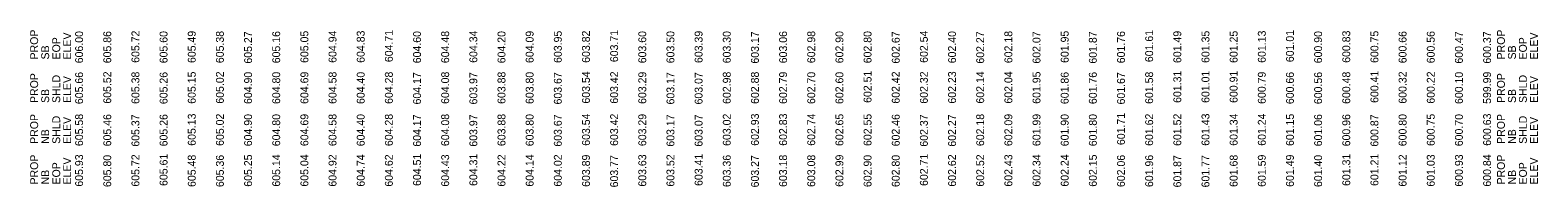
# Model space of a CAD drawing. Extents: x 24273 to 25612, y -285 to 1010.
# Drawn here: x 24273 to 25612, y -285 to -146 of the extents above; entities that cross this region are included whole.
import ezdxf

# ---------------------------------------------------------------- set-up
doc = ezdxf.new("R2010")
doc.units = 0
for name, color, linetype in [('PF_P_Text', 7, 'Continuous'), ('PF_P_Text_Strip_Grades_20', 7, 'Continuous'), ('PF_P_Text_Strip_Grades_LT', 7, 'Continuous'), ('PF_P_Text_Strip_Grades_RT', 7, 'Continuous')]:
    doc.layers.add(name, color=color, linetype=linetype)

msp = doc.modelspace()

# ---------------------------------------------------------------- texts
at = {"layer": 'PF_P_Text'}
for s, p in [('PROP ', (24280.4, -171.7)), ('PROP ', (25582.6, -171.7)), ('SB ', (24290.2, -171.7)), ('EOP', (24300, -171.7)), ('ELEV', (24309.7, -171.7)), ('SB ', (25592.4, -171.7)), ('EOP', (25602.1, -171.7)), ('ELEV', (25611.9, -171.7)), ('PROP ', (24280.4, -210.4)), ('SHLD ', (24300, -210.4)), ('ELEV', (24309.7, -210.4)), ('PROP ', (25582.6, -210.4)), ('SHLD', (25602.1, -210.4)), ('ELEV', (25611.9, -210.4)), ('SB ', (24290.2, -210.4)), ('SB ', (25592.4, -210.4)), ('PROP ', (24280.4, -246.7)), ('SHLD', (24300, -246.7)), ('ELEV', (24309.7, -246.7)), ('PROP ', (25582.6, -246.7)), ('SHLD', (25602.1, -246.7)), ('ELEV', (25611.9, -246.7)), ('NB ', (24290.2, -246.7)), ('NB ', (25592.4, -246.7)), ('PROP ', (24280.4, -282.8)), ('EOP', (24300, -282.8)), ('ELEV', (24309.7, -282.8)), ('PROP ', (25582.6, -282.8)), ('EOP', (25602.1, -282.8)), ('ELEV', (25611.9, -282.8)), ('NB ', (24290.2, -282.8)), ('NB ', (25592.4, -282.8))]:
    msp.add_text(s, height=7, rotation=90, dxfattribs=at).set_placement(p)
at = {"layer": 'PF_P_Text_Strip_Grades_20'}
for s, p in [('605.66', (24320.3, -211.4)), ('605.52', (24345.3, -211)), ('605.38', (24370.3, -211.2)), ('605.26', (24395.3, -211.4)), ('605.15', (24420.3, -211.1)), ('605.02', (24445.3, -211)), ('604.90', (24470.3, -211.3)), ('604.80', (24495.3, -211.3)), ('604.69', (24520.3, -211.2)), ('604.58', (24545.3, -211.2)), ('604.40', (24570.3, -211.3)), ('604.28', (24595.3, -211.2)), ('604.17', (24620.3, -211.7)), ('604.08', (24645.3, -211.2)), ('603.97', (24670.3, -211.7)), ('603.88', (24695.3, -211.2)), ('603.80', (24720.3, -211.3)), ('603.67', (24745.3, -211.7)), ('603.54', (24770.3, -210.9)), ('603.42', (24795.3, -211)), ('603.29', (24820.3, -211.2)), ('603.17', (24845.3, -211.7)), ('603.07', (24870.3, -211.7)), ('602.98', (24895.3, -211.2)), ('602.88', (24920.3, -211.2)), ('602.79', (24945.3, -211.2)), ('602.70', (24970.3, -211.3)), ('602.60', (24995.3, -211.3)), ('602.51', (25020.3, -210.3)), ('602.42', (25045.3, -211)), ('602.32', (25070.3, -211)), ('602.23', (25095.3, -210.9)), ('602.14', (25120.3, -210.9)), ('602.04', (25145.3, -210.9)), ('601.95', (25170.3, -211.1)), ('601.86', (25195.3, -211.4)), ('601.76', (25220.3, -211.4)), ('601.67', (25245.3, -211.7)), ('601.58', (25270.3, -211.2)), ('601.31', (25295.3, -210.3)), ('601.01', (25320.3, -210.3)), ('600.91', (25345.3, -210.3)), ('600.79', (25370.3, -211.2)), ('600.66', (25395.3, -211.4)), ('600.56', (25420.3, -211.4)), ('600.48', (25445.3, -211.2)), ('600.41', (25470.3, -210.3)), ('600.32', (25495.3, -211)), ('600.22', (25520.3, -211)), ('600.10', (25545.3, -211.3)), ('599.99', (25570.3, -211.2)), ('605.58', (24320.3, -248.7)), ('605.46', (24345.3, -248.9)), ('605.37', (24370.3, -249.2)), ('605.26', (24395.3, -248.9)), ('605.13', (24420.3, -248.4)), ('605.02', (24445.3, -248.5)), ('604.90', (24470.3, -248.8)), ('604.80', (24495.3, -248.8)), ('604.69', (24520.3, -248.7)), ('604.58', (24545.3, -248.7)), ('604.40', (24570.3, -248.8)), ('604.28', (24595.3, -248.7)), ('604.17', (24620.3, -249.2)), ('604.08', (24645.3, -248.7)), ('603.97', (24670.3, -249.2)), ('603.88', (24695.3, -248.7)), ('603.80', (24720.3, -248.8)), ('603.67', (24745.3, -249.2)), ('603.54', (24770.3, -248.4)), ('603.42', (24795.3, -248.5)), ('603.29', (24820.3, -248.7)), ('603.17', (24845.3, -249.2)), ('603.07', (24870.3, -249.2)), ('603.02', (24895.3, -248.5)), ('602.93', (24920.3, -248.4)), ('602.83', (24945.3, -248.4)), ('602.74', (24970.3, -248.4)), ('602.65', (24995.3, -248.6)), ('602.55', (25020.3, -248.6)), ('602.46', (25045.3, -248.9)), ('602.37', (25070.3, -249.2)), ('602.27', (25095.3, -249.2)), ('602.18', (25120.3, -248.7)), ('602.09', (25145.3, -248.7)), ('601.99', (25170.3, -248.7)), ('601.90', (25195.3, -248.8)), ('601.80', (25220.3, -248.8)), ('601.71', (25245.3, -247.8)), ('601.62', (25270.3, -248.5)), ('601.52', (25295.3, -248.5)), ('601.43', (25320.3, -248.4)), ('601.34', (25345.3, -248.4)), ('601.24', (25370.3, -248.4)), ('601.15', (25395.3, -248.6)), ('601.06', (25420.3, -248.9)), ('600.96', (25445.3, -248.9)), ('600.87', (25470.3, -249.2)), ('600.80', (25495.3, -248.8)), ('600.75', (25520.3, -248.6)), ('600.70', (25545.3, -248.8)), ('600.63', (25570.3, -248.4))]:
    msp.add_text(s, height=7, rotation=90, dxfattribs=at).set_placement(p)
at = {"layer": 'PF_P_Text_Strip_Grades_LT'}
for s, p in [('606.00', (24320.3, -175.1)), ('605.86', (24345.3, -175.1)), ('605.72', (24370.3, -174.7)), ('605.60', (24395.3, -175.1)), ('605.49', (24420.3, -174.9)), ('605.38', (24445.3, -175)), ('605.16', (24495.3, -175.1)), ('605.05', (24520.3, -174.8)), ('604.94', (24545.3, -174.7)), ('604.83', (24570.3, -174.7)), ('604.71', (24595.3, -174.1)), ('604.60', (24620.3, -175.1)), ('604.48', (24645.3, -175)), ('604.34', (24670.3, -174.7)), ('604.20', (24695.3, -175.1)), ('604.09', (24720.3, -174.9)), ('603.95', (24745.3, -174.8)), ('603.82', (24770.3, -174.7)), ('603.71', (24795.3, -174.1)), ('603.60', (24820.3, -175.1)), ('603.50', (24845.3, -175.1)), ('603.39', (24870.3, -174.9)), ('603.30', (24895.3, -175.1)), ('603.06', (24945.3, -175.1)), ('602.98', (24970.3, -175)), ('602.90', (24995.3, -175.1)), ('602.80', (25020.3, -175.1)), ('602.54', (25070.3, -174.7)), ('602.40', (25095.3, -175.1)), ('602.18', (25145.3, -175)), ('601.95', (25195.3, -174.8)), ('601.76', (25245.3, -175.1)), ('601.61', (25270.3, -174.1)), ('601.49', (25295.3, -174.9)), ('601.35', (25320.3, -174.8)), ('601.25', (25345.3, -174.8)), ('601.13', (25370.3, -174.7)), ('601.01', (25395.3, -174.1)), ('600.90', (25420.3, -175.1)), ('600.83', (25445.3, -174.7)), ('600.75', (25470.3, -174.8)), ('600.66', (25495.3, -175.1)), ('600.56', (25520.3, -175.1)), ('605.27', (24470.3, -175.4)), ('603.17', (24920.3, -175.4)), ('602.67', (25045.3, -175.4)), ('602.27', (25120.3, -175.4)), ('602.07', (25170.3, -175.4)), ('601.87', (25220.3, -175.4)), ('600.47', (25545.3, -175.4)), ('600.37', (25570.3, -175.4))]:
    msp.add_text(s, height=7, rotation=90, dxfattribs=at).set_placement(p)
at = {"layer": 'PF_P_Text_Strip_Grades_RT'}
for s, p in [('605.93', (24320.3, -284.7)), ('605.80', (24345.3, -285.1)), ('605.72', (24370.3, -284.7)), ('605.61', (24395.3, -284.1)), ('605.48', (24420.3, -285)), ('605.36', (24445.3, -285.1)), ('605.25', (24470.3, -284.8)), ('605.14', (24495.3, -284.7)), ('605.04', (24520.3, -284.7)), ('604.92', (24545.3, -284.7)), ('604.74', (24570.3, -284.7)), ('604.62', (24595.3, -284.7)), ('604.51', (24620.3, -284.1)), ('604.43', (24645.3, -284.7)), ('604.31', (24670.3, -284.1)), ('604.22', (24695.3, -284.7)), ('604.14', (24720.3, -284.7)), ('604.02', (24745.3, -284.7)), ('603.89', (24770.3, -284.9)), ('603.77', (24795.3, -285.4)), ('603.63', (24820.3, -284.7)), ('603.52', (24845.3, -284.7)), ('603.41', (24870.3, -284.1)), ('603.36', (24895.3, -285.1)), ('603.27', (24920.3, -285.4)), ('603.18', (24945.3, -285)), ('603.08', (24970.3, -285)), ('602.99', (24995.3, -284.9)), ('602.90', (25020.3, -285.1)), ('602.80', (25045.3, -285.1)), ('602.71', (25070.3, -284.1)), ('602.62', (25095.3, -284.7)), ('602.52', (25120.3, -284.7)), ('602.43', (25145.3, -284.7)), ('602.34', (25170.3, -284.7)), ('602.24', (25195.3, -284.7)), ('602.15', (25220.3, -284.8)), ('602.06', (25245.3, -285.1)), ('601.96', (25270.3, -285.1)), ('601.87', (25295.3, -285.4)), ('601.77', (25320.3, -285.4)), ('601.68', (25345.3, -285)), ('601.59', (25370.3, -284.9)), ('601.49', (25395.3, -284.9)), ('601.40', (25420.3, -285.1)), ('601.31', (25445.3, -284.1)), ('601.21', (25470.3, -284.1)), ('601.12', (25495.3, -284.7)), ('601.03', (25520.3, -284.7)), ('600.93', (25545.3, -284.7)), ('600.84', (25570.3, -284.7))]:
    msp.add_text(s, height=7, rotation=90, dxfattribs=at).set_placement(p)

doc.saveas('drawing.dxf')
